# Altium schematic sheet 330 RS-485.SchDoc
size Letter; Organization: Toradex Solutions Inc.; Address1: 6415 Northwest Drive; Address2: Mississauga, ON, L4V 1X1; Address3: Canada
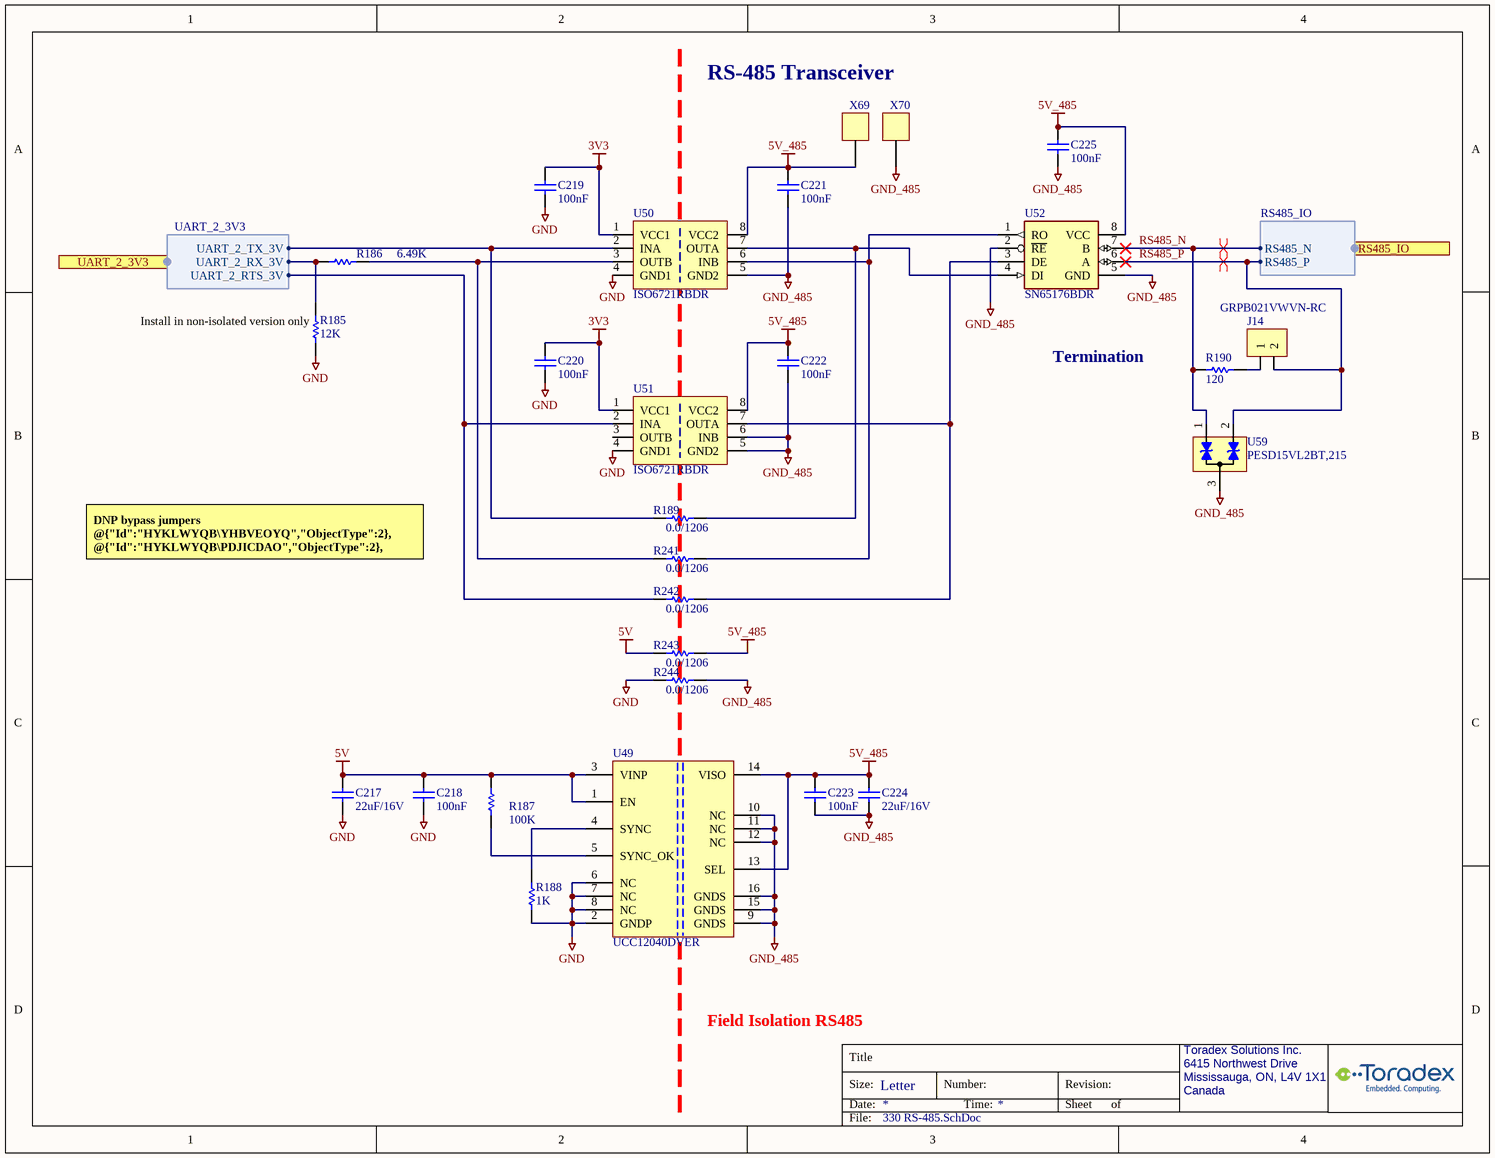
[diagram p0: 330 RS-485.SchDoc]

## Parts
C217  value 22uF/16V  [C/0805]  (hidden comment: 1314-Cap-0805-22uF/16V)
C218  100nF  [C0402_CAPC1005L]
C219  100nF  [C0402_CAPC1005L]
C220  100nF  [C0402_CAPC1005L]
C221  100nF  [C0402_CAPC1005L]
C222  100nF  [C0402_CAPC1005L]
C223  100nF  [C0402_CAPC1005L]
C224  value 22uF/16V  [C/0805]  (hidden comment: 1314-Cap-0805-22uF/16V)
C225  100nF  [C0402_CAPC1005L]
J14  GRPB021VWVN-RC  [CONN_WVN-RC_SUL]
R185  value 12K  [R0402_RESC1005L]  (hidden comment: 1537-Res-0402-12K)
R186  value 6.49K  [R0402_RESC1005L]  (hidden comment: 1018-Res-0402-6.49K)
R187  value 100K  [R0402_RESC1005L]  (hidden comment: 1977-Res-0402-100K)
R188  value 1K  [R0402_RESC1005L]  (hidden comment: 1650-Res-0402-1K)
R189  value 0.0/1206  [R/1206]  (hidden comment: 0038-Res-1206-0.0ohm)
R190  value 120  [R0402_RESC1005L]  (hidden comment: 1552-Res-0402-120)
R241  value 0.0/1206  [R/1206]  (hidden comment: 0038-Res-1206-0.0ohm)
R242  value 0.0/1206  [R/1206]  (hidden comment: 0038-Res-1206-0.0ohm)
R243  value 0.0/1206  [R/1206]  (hidden comment: 0038-Res-1206-0.0ohm)
R244  value 0.0/1206  [R/1206]  (hidden comment: 0038-Res-1206-0.0ohm)
U49  UCC12040DVER  [SOIC-16]
U50  ISO6721RBDR  [SOIC-8]
U51  ISO6721RBDR  [SOIC-8]
U52  SN65176BDR  [SOIC-8]
U59  PESD15VL2BT,215  [SOT23_N]
X69  000-TestPoint  [TestPoint_1]  (value not drawn)
X70  000-TestPoint  [TestPoint_1]  (value not drawn)

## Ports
RS485_IO (harness RS485_IO), UART_2_3V3 (harness UART_2_3V3)

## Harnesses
UART_2_3V3: UART_2_RX_3V, UART_2_TX_3V, UART_2_RTS_3V
RS485_IO: RS485_N, RS485_P

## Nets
3V3: C219.1 C220.1 U50.1(VCC1) U51.1(VCC1)
5V: C217.2 C218.1 R187.2 R243.2 U49.1(EN) U49.3(VINP)
5V_485: C221.1 C222.1 C223.1 C224.2 C225.1 R243.1 U49.13(SEL) U49.14(VISO) U50.8(VCC2) U51.8(VCC2) U52.8(VCC) X69.1
GND: C217.1 C218.2 C219.2 C220.2 R185.1 R188.1 R244.2 U49.2(GNDP) U49.6(NC) U49.7(NC) U49.8(NC) U50.4(GND1) U51.4(GND1)
GND_485: C221.2 C222.2 C223.2 C224.1 C225.2 R244.1 U49.9(GNDS) U49.10(NC) U49.11(NC) U49.12(NC) U49.15(GNDS) U49.16(GNDS) U50.5(GND2) U51.5(GND2) U51.6(INB) U52.2(~{RE}) U52.5(GND) U59.3(CC) X70.1
RS485_N: R190.1 U52.7(B) U59.1(K1) ; port RS485_IO.RS485_N
RS485_P: J14.2 U52.6(A) U59.2(K2) ; port RS485_IO.RS485_P
NetJ14_1: J14.1 R190.2
NetR185_2: R185.2 R186.2 ; port UART_2_3V3.UART_2_RX_3V
NetR186_1: R186.1 R241.2 U50.3(OUTB)
NetR187_1: R187.1 U49.5(SYNC_OK)
NetR188_2: R188.2 U49.4(SYNC)
NetR189_1: R189.1 U50.7(OUTA) U52.4(DI)
NetR189_2: R189.2 U50.2(INA) ; port UART_2_3V3.UART_2_TX_3V
NetR241_1: R241.1 U50.6(INB) U52.1(RO)
NetR242_1: R242.1 U51.7(OUTA) U52.3(DE)
NetR242_2: R242.2 U51.2(INA) ; port UART_2_3V3.UART_2_RTS_3V

Not connected (* = marked no-connect by the designer): U51 3(OUTB)

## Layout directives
differential pair; differential pair class RS485: RS485_N, RS485_P

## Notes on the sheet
- RS-485 Transceiver
- (near R185) Install in non-isolated version only
- Termination
- DNP bypass jumpers @{"Id":"HYKLWYQB\YHBVEOYQ","ObjectType":2}, @{"Id":"HYKLWYQB\PDJICDAO","ObjectType":2}, @{"Id":"HYKLWYQB\NNRCJBDI","ObjectType":2}, @{"Id":"HYKLWYQB\DUEUYHHI","ObjectType":2} and @{"Id":"HYKLWYQB\VTBHMBYQ","ObjectType":2} if @{"Id":"HYKLWYQB\RAJTRIYT"} , @{"Id":"HYKLWYQB\KFGBLUON"} and @{"Id":"HYKLWYQB\TYSTDRWN"} are't mounted.
  Ground isolation is not provided in that case.
- Field Isolation RS485

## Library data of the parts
C217 C224 = 1314-Cap-0805-22uF/16V: (-55 to 85 DegC) CAP CER 22uF 16V X5R 0805; MfrNo: CL21A226MOQNNNE; Mfr: Samsung; PN: 1314; Alt: CL21A226MOCLRNC,CL21A226KOQNNNG,GRM21BR61C226ME44L,EMK212BBJ226MG-T
C218-C223 C225 = 1566-Cap-0402-100nF/50V: (-55 to 125 DegC AEC) Cap Ceramic 0.1uF 50V X7R 10% 0402; MfrNo: GRT155R71H104KE01D; Mfr: Murata; Alt: CL05B104KB54PNC,GCM155R71H104ME02D,GCM155R71H104KE02D,GCM155R71H104KE02J; PN: 1566
J14 = 2350-CONN HEADER VERT 2POS 1.27MM: (-40 to 105 DegC) CONN HEADER VERT 2POS 1.27MM GOLD; Mfr: Sullins; PN: 2350
R185 = 1537-Res-0402-12K: (-55 to 155 DegC AEC) RES 12K OHM 1% 1/16W 100ppm 0402; Mfr: Stackpole Electronics; MfrNo: RMCF0402FT12K0; Alt: AC0402FR-0712KL,CRGCQ0402F12K; PN: 1537
R186 = 1018-Res-0402-6.49K: (-55 to 155 DegC) RES SMD 6.49K OHM 1% 1/16W 0402; Mfr: Yageo; MfrNo: RC0402FR-076K49L; Alt: RMCF0402FT6K49,RC1005F6491CS,ERJ-2RKF6491X; PN: 1018
R187 = 1977-Res-0402-100K: (-55 to 155 DegC) RES 100K OHM 1/16W 1% 0402 SMD; Mfr: Yageo; MfrNo: RC0402FR-07100KL; PN: 1977
R188 = 1650-Res-0402-1K: (-55 to 155 DegC AEC) RES 1K OHM 1% 1/16W 100ppm 0402; Mfr: TE Connectivity; MfrNo: CRGCQ0402F1K0; PN: 1650; Alt: CR0402AFX-1001GLF,AC0402FR-131KL,AC0402FR-071KL
R189 R241-R244 = 0038-Res-1206-0.0ohm: (-55 to 155 DegC) RES 0.0 OHM 1/4W JUMPER 1206; Mfr: TE; MfrNo: 1623693-1; PN: 38; Alt: 311-0.0ERCT-ND; Alt2: RMCF1206ZT0R00CT-ND
R190 = 1552-Res-0402-120: (-55 to 155 DegC AEC) RES 120 OHM 1% 1/16W 100ppm 0402; Mfr: Stackpole Electronics; MfrNo: RMCF0402FT120R; PN: 1552; Alt: AC0402FR-07120RL,CRGCQ0402F120R
U49 = 2065-UCC12040DVER: (-40 to 125 DegC) IC Isolated DC DC Converter-Output 3.3V, 5V 140mA, 4.5V-5.5V Input; Mfr: Texas Instruments; PN: 2065
U50 U51 = 2198-ISO6721RBDR: (-40 to 125 DegC) IC DGTL ISO GENERAL-PURPOSE, DUAL-CHANNEL, 1x In, 1x Out 1.71-5.5V; Mfr: Texas Instruments; PN: 2198
U52 = 2071-SN65176BDR: (-40 to 125 DegC) IC TXRX 5V RS485/422 8-SOIC; Mfr: Texas Instruments; PN: 2071
U59 = 2239-PESD15VL2BT,215: (-65 to 150 DegC) TVS DIODE 2-CH 15VWM 44VC ESD:30KV TO236AB; Mfr: Nexperia; PN: 2239
X69 X70 = 000-TestPoint: Note: this is PCB footprint only, no parts to buy or assemble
